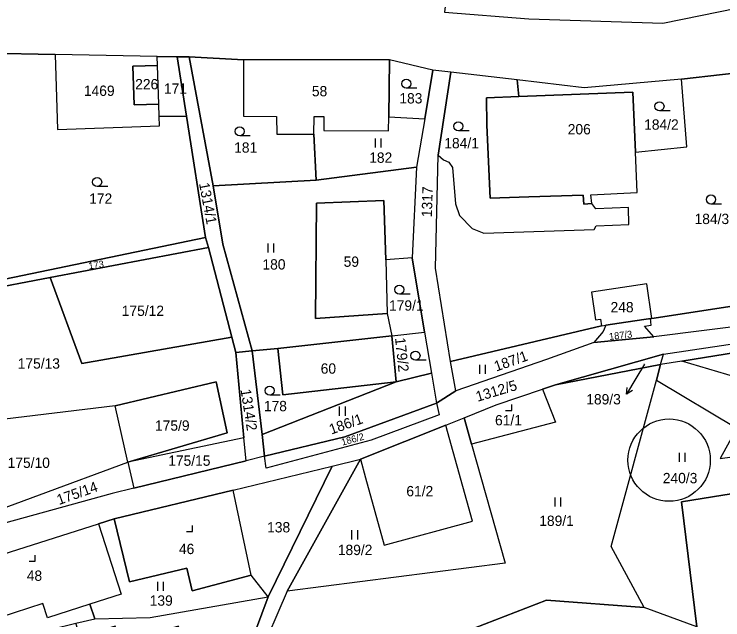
# Model space of a CAD drawing. Extents: x -588699 to -585793, y -1060280 to -1056731.
# Drawn here: x -588042.9 to -587926.2, y -1058215 to -1058115.3 of the extents above; entities that cross this region are included whole.
import ezdxf

# ---------------------------------------------------------------- set-up
doc = ezdxf.new("R2010")
doc.units = 0
for name, color, linetype in [('Druh pozemku', 7, 'Continuous'), ('Parcela nároku', 7, 'Continuous'), ('Parcelní číslo', 7, 'Continuous'), ('Změna katastrální hranice', 7, 'Continuous')]:
    doc.layers.add(name, color=color, linetype=linetype)

msp = doc.modelspace()

# ---------------------------------------------------------------- linework, layer by layer
at = {"layer": 'Druh pozemku'}
for p, q in [((-587976.62, -1058127.5), (-587978.37, -1058127.5)), ((-587934.93, -1058131.23), (-587936.68, -1058131.23)), ((-587968.03, -1058134.51), (-587969.78, -1058134.51)), ((-588004.04, -1058135.36), (-588005.79, -1058135.36)), ((-587983.51, -1058135.76), (-587983.51, -1058137.26)), ((-587982.48, -1058137.26), (-587982.48, -1058135.76)), ((-588027.51, -1058143.7), (-588029.26, -1058143.7)), ((-587926.45, -1058146.57), (-587928.2, -1058146.57)), ((-588001.18, -1058153.07), (-588001.18, -1058154.57)), ((-588000.16, -1058154.57), (-588000.16, -1058153.07)), ((-587977.74, -1058161.42), (-587979.49, -1058161.42)), ((-587975.1, -1058172.28), (-587976.85, -1058172.28)), ((-587966.33, -1058173.04), (-587966.33, -1058174.54)), ((-587965.31, -1058174.54), (-587965.31, -1058173.04)), ((-587999.1, -1058178.05), (-588000.85, -1058178.05)), ((-587989.4, -1058179.93), (-587989.4, -1058181.43)), ((-587988.38, -1058181.43), (-587988.38, -1058179.93)), ((-587933.46, -1058187.53), (-587933.46, -1058189.03)), ((-587932.44, -1058189.03), (-587932.44, -1058187.53)), ((-587953.92, -1058194.89), (-587953.92, -1058196.39)), ((-587952.9, -1058196.39), (-587952.9, -1058194.89)), ((-587987.36, -1058200.3), (-587987.36, -1058201.8)), ((-587986.33, -1058201.8), (-587986.33, -1058200.3)), ((-588019.33, -1058208.76), (-588019.33, -1058210.26)), ((-588018.31, -1058210.26), (-588018.31, -1058208.76))]:
    msp.add_line(p, q, dxfattribs=at)
for points in [[(-587962, -1058180.56), (-587961, -1058180.56), (-587961, -1058179.56)], [(-588014.55, -1058200.49), (-588013.55, -1058200.49), (-588013.55, -1058199.49)], [(-588040.46, -1058205.41), (-588039.46, -1058205.41), (-588039.46, -1058204.41)]]:
    msp.add_lwpolyline(points, dxfattribs=at)
for centre in [(-587978.37, -1058126.75), (-587936.68, -1058130.48), (-587969.78, -1058133.76), (-588005.79, -1058134.61), (-588029.26, -1058142.95), (-587928.2, -1058145.82), (-587979.49, -1058160.67), (-587976.85, -1058171.53), (-588000.85, -1058177.3)]:
    msp.add_circle(centre, 0.75, dxfattribs=at)
at = {"layer": 'Parcela nároku'}
for points in [[(-587905.27, -1058107.44), (-587957.76, -1058103.14), (-587957.46, -1058105.34), (-587971.28, -1058108.32), (-587972.07, -1058115), (-587958.19, -1058116.05), (-587936.11, -1058116.81), (-587902.41, -1058109.85)], [(-588014.55, -1058132.08), (-588011.42, -1058152.1), (-588048.73, -1058159.83), (-588048.14, -1058143.2), (-588047.38, -1058121.73), (-588036.18, -1058121.95), (-588035.78, -1058134.31), (-588019, -1058133.7), (-588019.05, -1058132.15)], [(-588019, -1058133.7), (-588019.05, -1058132.15), (-588019.12, -1058130.13), (-588023.16, -1058130.21), (-588023.37, -1058123.84), (-588019.33, -1058123.76), (-588019.38, -1058122.28), (-588036.18, -1058121.95), (-588035.78, -1058134.31)], [(-588019.38, -1058122.28), (-588016.07, -1058122.34), (-588014.55, -1058132.08), (-588019.05, -1058132.15), (-588019.12, -1058130.13), (-588019.33, -1058123.76)], [(-588010.17, -1058143.59), (-588008.57, -1058153.18), (-588003.75, -1058170.75), (-588006.42, -1058171.01), (-588007.07, -1058168.5), (-588010.91, -1058153.75), (-588011.42, -1058152.1), (-588014.55, -1058132.08), (-588016.07, -1058122.34), (-588014.09, -1058122.32)], [(-587999.7, -1058135.06), (-587993.56, -1058135.06), (-587993.21, -1058142.62), (-588010.17, -1058143.59), (-588014.09, -1058122.32), (-588005.14, -1058122.81), (-588005.15, -1058132.1), (-587999.73, -1058132.15)], [(-588005.14, -1058122.81), (-588005.15, -1058132.1), (-587999.73, -1058132.15), (-587999.7, -1058135.06), (-587993.56, -1058135.06), (-587993.53, -1058132.14), (-587991.91, -1058132.15), (-587991.92, -1058134.48), (-587981.28, -1058134.52), (-587981.23, -1058132.19), (-587981.13, -1058122.84)], [(-587973.98, -1058124.5), (-587981.13, -1058122.84), (-587981.23, -1058132.19), (-587975.33, -1058132.52)], [(-588019.12, -1058130.13), (-588019.33, -1058123.76), (-588023.37, -1058123.84), (-588023.16, -1058130.21)], [(-587971.1, -1058172.51), (-587973.57, -1058157.13), (-587973.1, -1058138.54), (-587971.04, -1058124.84), (-587973.98, -1058124.5), (-587975.33, -1058132.52), (-587976.68, -1058140.49), (-587977.42, -1058155.41), (-587975.36, -1058167.68), (-587974.22, -1058174.45), (-587973.4, -1058179.35), (-587970.19, -1058177.31)], [(-587958.16, -1058145.41), (-587964.55, -1058145.63), (-587965.1, -1058133.6), (-587965.16, -1058129.09), (-587959.84, -1058128.88), (-587960.12, -1058126.1), (-587971.04, -1058124.84), (-587973.1, -1058138.54), (-587972.24, -1058139.31), (-587971.37, -1058139.69), (-587970.75, -1058140.58), (-587970.26, -1058146.51), (-587969.6, -1058148.46), (-587967.49, -1058150.61), (-587965.61, -1058151.36), (-587947.41, -1058150.75), (-587947.11, -1058150.15), (-587941.73, -1058149.94), (-587941.8, -1058147.14), (-587947.17, -1058147.37), (-587947.79, -1058146.5), (-587949.14, -1058146.57), (-587949.23, -1058145.1)], [(-587932.17, -1058137.14), (-587933.06, -1058125.98), (-587949.07, -1058127.46), (-587960.12, -1058126.1), (-587959.84, -1058128.88), (-587941.08, -1058128.16), (-587940.64, -1058138.05)], [(-587940.34, -1058144.65), (-587940.64, -1058138.05), (-587941.08, -1058128.16), (-587959.84, -1058128.88), (-587965.16, -1058129.09), (-587965.1, -1058133.6), (-587964.55, -1058145.63), (-587958.16, -1058145.41), (-587949.23, -1058145.1), (-587949.14, -1058146.57), (-587947.79, -1058146.5), (-587947.99, -1058145.07)], [(-587993.53, -1058132.14), (-587991.91, -1058132.15), (-587991.92, -1058134.48), (-587981.28, -1058134.52), (-587981.23, -1058132.19), (-587975.33, -1058132.52), (-587976.68, -1058140.49), (-587993.21, -1058142.62), (-587993.56, -1058135.06)], [(-587981.5, -1058164.62), (-587980.73, -1058168.26), (-587999.52, -1058170.38), (-588003.75, -1058170.75), (-588008.57, -1058153.18), (-588010.17, -1058143.59), (-587993.21, -1058142.62), (-587976.68, -1058140.49), (-587977.42, -1058155.41), (-587981.75, -1058155.74), (-587982.03, -1058146.01), (-587993.12, -1058146.43), (-587993.28, -1058165.44)], [(-587993.12, -1058146.43), (-587982.03, -1058146.01), (-587981.75, -1058155.74), (-587981.5, -1058164.62), (-587993.28, -1058165.44)], [(-588011.42, -1058152.1), (-588010.91, -1058153.75), (-588036.97, -1058158.68), (-588048.49, -1058160.86), (-588048.73, -1058159.83)], [(-588036.97, -1058158.68), (-588010.91, -1058153.75), (-588007.07, -1058168.5), (-588031.79, -1058172.85)], [(-587977.42, -1058155.41), (-587981.75, -1058155.74), (-587981.5, -1058164.62), (-587980.73, -1058168.26), (-587975.36, -1058167.68)], [(-588036.97, -1058158.68), (-588031.79, -1058172.85), (-588007.07, -1058168.5), (-588006.42, -1058171.01), (-588005.12, -1058185.1), (-588024.21, -1058189.07), (-588007.87, -1058184.23), (-588009.65, -1058175.86), (-588026.28, -1058179.79), (-588046.31, -1058182.23), (-588047.18, -1058174.61), (-588060.82, -1058175.82), (-588064.06, -1058164.47), (-588048.49, -1058160.86)], [(-587937.93, -1058165.4), (-587938.77, -1058159.7), (-587947.88, -1058161.1), (-587947.21, -1058165.65), (-587946.41, -1058165.53), (-587946.23, -1058166.64), (-587945.49, -1058166.52), (-587944.4, -1058166.36), (-587943.34, -1058166.2), (-587939.28, -1058165.6), (-587938.5, -1058165.49), (-587938.13, -1058165.42)], [(-587937.93, -1058165.4), (-587904.02, -1058160.23), (-587904, -1058164.19), (-587937.63, -1058168.42), (-587939.12, -1058166.7), (-587938.04, -1058166.53), (-587938.13, -1058165.42)], [(-587937.19, -1058175.57), (-587923.93, -1058183.49), (-587926.7, -1058188.48), (-587898.86, -1058184.66), (-587888.94, -1058185.21), (-587884.21, -1058183.4), (-587886.93, -1058176.48), (-587883.4, -1058175.08), (-587886.16, -1058167.86), (-587887.26, -1058165.09), (-587878.46, -1058165.39), (-587874.84, -1058186.24), (-587933.04, -1058195.62), (-587930.55, -1058216.22), (-587939.22, -1058213.03), (-587944.64, -1058202.99)], [(-587887.26, -1058165.09), (-587903.82, -1058167.75), (-587903.56, -1058168.92), (-587919.66, -1058176.42), (-587933.02, -1058172.44), (-587936.49, -1058173), (-587937.19, -1058175.57), (-587923.93, -1058183.49), (-587926.7, -1058188.48), (-587898.86, -1058184.66), (-587903.56, -1058174.48), (-587886.16, -1058167.86)], [(-587936.03, -1058171.3), (-587904.1, -1058166.51), (-587887.26, -1058165.09), (-587903.82, -1058167.75), (-587933.02, -1058172.44), (-587936.49, -1058173)], [(-587945.97, -1058167.58), (-587947.48, -1058169.39), (-587937.63, -1058168.42), (-587939.12, -1058166.7), (-587938.04, -1058166.53), (-587938.13, -1058165.42), (-587938.5, -1058165.49), (-587939.28, -1058165.6), (-587943.34, -1058166.2), (-587944.4, -1058166.36), (-587945.49, -1058166.52)], [(-587878.46, -1058165.39), (-587852.6, -1058169.68), (-587842.96, -1058169.39), (-587845.87, -1058217.7), (-587852.17, -1058218.46), (-587874.99, -1058223.36), (-587893.08, -1058224.69), (-587921.7, -1058222.21), (-587922.75, -1058226.1), (-587927.3, -1058243.08), (-587929.2, -1058227.37), (-587930.55, -1058216.22), (-587933.04, -1058195.62), (-587874.84, -1058186.24)], [(-587971.1, -1058172.51), (-587946.23, -1058166.64), (-587945.49, -1058166.52), (-587945.97, -1058167.58), (-587947.48, -1058169.39), (-587955.25, -1058172.16), (-587970.19, -1058177.31)], [(-587980.73, -1058168.26), (-587980.05, -1058175.87), (-587998.67, -1058177.99), (-587999.52, -1058170.38)], [(-587975.36, -1058167.68), (-587974.22, -1058174.45), (-587980.05, -1058175.87), (-587980.73, -1058168.26)], [(-587903.82, -1058167.75), (-587903.56, -1058168.92), (-587919.66, -1058176.42), (-587933.02, -1058172.44)], [(-588002.11, -1058184.55), (-588001.69, -1058188.1), (-588004.73, -1058188.84), (-588005.12, -1058185.1), (-588006.42, -1058171.01), (-588003.75, -1058170.75)], [(-588003.75, -1058170.75), (-587999.52, -1058170.38), (-587998.67, -1058177.99), (-587980.05, -1058175.87), (-588002.11, -1058184.55)], [(-587936.03, -1058171.3), (-587953.79, -1058176.32), (-587936.49, -1058173)], [(-587962.1, -1058205.72), (-587997.97, -1058210.3), (-588002.76, -1058221.42), (-588002.42, -1058228.61), (-587986.11, -1058221.3), (-587982.5, -1058222.32), (-587955.25, -1058211.83), (-587939.22, -1058213.03), (-587944.64, -1058202.99), (-587937.19, -1058175.57), (-587936.49, -1058173), (-587953.79, -1058176.32), (-587955.95, -1058177.06), (-587953.8, -1058182.5), (-587967.62, -1058186.12)], [(-587974.22, -1058174.45), (-587973.4, -1058179.35), (-587988.48, -1058184.92), (-588001.69, -1058188.1), (-588002.11, -1058184.55), (-587980.05, -1058175.87)], [(-588009.65, -1058175.86), (-588007.87, -1058184.23), (-588024.21, -1058189.07), (-588026.28, -1058179.79)], [(-587955.95, -1058177.06), (-587953.8, -1058182.5), (-587967.62, -1058186.12), (-587968.85, -1058181.77), (-587963.54, -1058179.65)], [(-588024.21, -1058189.07), (-588026.28, -1058179.79), (-588046.31, -1058182.23), (-588057.57, -1058186.43), (-588053.33, -1058199.85)], [(-587988.48, -1058184.92), (-587973.4, -1058179.35), (-587972.95, -1058181.31), (-587984.15, -1058185.44), (-588001.45, -1058190.08), (-588001.69, -1058188.1)], [(-587971.86, -1058182.98), (-587968.85, -1058181.77), (-587967.62, -1058186.12), (-587962.1, -1058205.72), (-587997.97, -1058210.3), (-587985.91, -1058188.6), (-587985.06, -1058191.68), (-587982.01, -1058202.74), (-587967.46, -1058198.8), (-587971.57, -1058184.04)], [(-587978.59, -1058185.67), (-587985.91, -1058188.6), (-587985.06, -1058191.68), (-587982.01, -1058202.74), (-587967.46, -1058198.8), (-587971.57, -1058184.04), (-587971.86, -1058182.98)], [(-588005.12, -1058185.1), (-588024.21, -1058189.07), (-588023.22, -1058193.36), (-588004.73, -1058188.84)], [(-588024.21, -1058189.07), (-588023.22, -1058193.36), (-588026.8, -1058194.23), (-588052.9, -1058201.43), (-588053.33, -1058199.85)], [(-588006.88, -1058193.67), (-587990.55, -1058189.72), (-588001.08, -1058211.26), (-588003.88, -1058207.71)], [(-588003.88, -1058207.71), (-588006.88, -1058193.67), (-588026.47, -1058198.42), (-588023.93, -1058208.8), (-588014.49, -1058206.52), (-588013.59, -1058210.28)], [(-588023.93, -1058208.8), (-588026.47, -1058198.42), (-588029.03, -1058199.24), (-588025.28, -1058210.8), (-588030.46, -1058212.46), (-588029.61, -1058214.86), (-588020.54, -1058214.66), (-588001.08, -1058211.26), (-588003.88, -1058207.71), (-588013.59, -1058210.28), (-588014.49, -1058206.52)], [(-588048.39, -1058205.39), (-588029.03, -1058199.24), (-588025.28, -1058210.8), (-588030.46, -1058212.46), (-588037.44, -1058214.7), (-588038.19, -1058212.33), (-588045.35, -1058214.64)], [(-588037.44, -1058214.7), (-588038.19, -1058212.33), (-588045.35, -1058214.64), (-588048.39, -1058205.39), (-588058.38, -1058208.56), (-588053.92, -1058217.06), (-588052.23, -1058220.29), (-588047.8, -1058219.23), (-588036.77, -1058216.58), (-588032.79, -1058215.62), (-588029.61, -1058214.86), (-588030.46, -1058212.46)], [(-588032.79, -1058215.62), (-588029.61, -1058214.86), (-588020.54, -1058214.66), (-588001.08, -1058211.26), (-588005.42, -1058222.88), (-588013.42, -1058225.65), (-588015.88, -1058216.1), (-588025.29, -1058218.83), (-588026.29, -1058216.07), (-588032.03, -1058217.82)], [(-587939.22, -1058213.03), (-587955.25, -1058211.83), (-587982.5, -1058222.32), (-587986.11, -1058221.3), (-588002.42, -1058228.61), (-588002.11, -1058235.37), (-587998.02, -1058244.21), (-587982.98, -1058242.73), (-587929.2, -1058227.37), (-587930.55, -1058216.22)]]:
    msp.add_lwpolyline(points, close=True, dxfattribs=at)
for points in [[(-587879.59, -1058109.01), (-587910.22, -1058119.99), (-587919.57, -1058124.47), (-587933.06, -1058125.98), (-587949.07, -1058127.46), (-587960.12, -1058126.1), (-587971.04, -1058124.84), (-587973.98, -1058124.5), (-587981.13, -1058122.84), (-588005.14, -1058122.81), (-588014.09, -1058122.32), (-588016.07, -1058122.34), (-588019.38, -1058122.28), (-588036.18, -1058121.95), (-588047.38, -1058121.73), (-588054.87, -1058121.87), (-588058.28, -1058121.93), (-588062.02, -1058121.79), (-588073.1, -1058121.39), (-588081.23, -1058121.1), (-588115.84, -1058119.95), (-588127.93, -1058119.84), (-588133.87, -1058117.14), (-588172.01, -1058109.5)], [(-587972.07, -1058115), (-587958.19, -1058116.05), (-587936.11, -1058116.81), (-587902.41, -1058109.85)], [(-587904.02, -1058160.23), (-587937.93, -1058165.4), (-587938.77, -1058159.7), (-587947.88, -1058161.1), (-587947.21, -1058165.65), (-587946.41, -1058165.53), (-587946.23, -1058166.64), (-587971.1, -1058172.51), (-587973.57, -1058157.13), (-587973.1, -1058138.54), (-587972.24, -1058139.31), (-587971.37, -1058139.69), (-587970.75, -1058140.58), (-587970.26, -1058146.51), (-587969.6, -1058148.46), (-587967.49, -1058150.61), (-587965.61, -1058151.36), (-587947.41, -1058150.75), (-587947.11, -1058150.15), (-587941.73, -1058149.94), (-587941.8, -1058147.14), (-587947.17, -1058147.37), (-587947.79, -1058146.5), (-587947.99, -1058145.07), (-587940.34, -1058144.65), (-587940.64, -1058138.05), (-587932.17, -1058137.14), (-587933.06, -1058125.98), (-587919.57, -1058124.47)], [(-587808.9, -1058162.63), (-587840.39, -1058167.44), (-587852.03, -1058167.69), (-587888.68, -1058161.9), (-587901.92, -1058163.88), (-587904, -1058164.19), (-587937.63, -1058168.42), (-587947.48, -1058169.39), (-587955.25, -1058172.16), (-587970.19, -1058177.31), (-587973.4, -1058179.35), (-587972.95, -1058181.31), (-587984.15, -1058185.44), (-588001.45, -1058190.08), (-588001.69, -1058188.1), (-588004.73, -1058188.84), (-588023.22, -1058193.36), (-588026.8, -1058194.23), (-588052.9, -1058201.43)], [(-588048.39, -1058205.39), (-588029.03, -1058199.24), (-588026.47, -1058198.42), (-588006.88, -1058193.67), (-587990.55, -1058189.72), (-587985.91, -1058188.6), (-587978.59, -1058185.67), (-587971.86, -1058182.98), (-587968.85, -1058181.77), (-587963.54, -1058179.65), (-587955.95, -1058177.06), (-587953.79, -1058176.32), (-587936.03, -1058171.3), (-587904.1, -1058166.51), (-587887.26, -1058165.09), (-587878.46, -1058165.39), (-587852.6, -1058169.68), (-587842.96, -1058169.39), (-587834.19, -1058169.13), (-587817.41, -1058167.23)], [(-588043.9, -1058278.57), (-588040.35, -1058274.68), (-588035.53, -1058269.41), (-588026.72, -1058262.49), (-588019.94, -1058256.55), (-588010.93, -1058249.05), (-588005.9, -1058234.96), (-588005.42, -1058222.88), (-588001.08, -1058211.26), (-587990.55, -1058189.72), (-587985.91, -1058188.6), (-587997.97, -1058210.3), (-588002.76, -1058221.42), (-588002.42, -1058228.61), (-588002.11, -1058235.37), (-588006.72, -1058248.64), (-588010.89, -1058252.97), (-588013.86, -1058255.37), (-588014.78, -1058256.14), (-588032.33, -1058270.74), (-588037.18, -1058276.01), (-588042.26, -1058285.27)]]:
    msp.add_lwpolyline(points, dxfattribs=at)
at = {"layer": 'Parcelní číslo'}
for p, q in [((-587939.17, -1058172.96), (-587940.55, -1058175.29)), ((-587940.55, -1058175.29), (-587942.08, -1058177.87))]:
    msp.add_line(p, q, dxfattribs=at)
msp.add_lwpolyline([(-587941.14, -1058177.27), (-587942.08, -1058177.87), (-587942, -1058176.76)], dxfattribs=at)
at = {"layer": 'Změna katastrální hranice'}
msp.add_circle((-587935.09, -1058188.75), 6.78, dxfattribs=at)

# ---------------------------------------------------------------- texts
at = {"layer": 'Parcela nároku'}
for s, height, p in [('226', 1.7, (-588022.99, -1058127.68)), ('1469', 1.7, (-588031.44, -1058128.76)), ('171', 1.7, (-588018.26, -1058128.41)), ('58', 1.7, (-587993.9, -1058128.83)), ('183', 1.7, (-587979.5, -1058130.01)), ('206', 1.7, (-587951.78, -1058135.1)), ('184/2', 1.7, (-587939.2, -1058134.33)), ('184/1', 1.7, (-587972.1, -1058137.39)), ('181', 1.7, (-588006.7, -1058138.11)), ('182', 1.7, (-587984.47, -1058139.78)), ('172', 1.7, (-588030.57, -1058146.53)), ('184/3', 1.7, (-587930.9, -1058149.87)), ('180', 1.7, (-588002.04, -1058157.36)), ('59', 1.7, (-587988.67, -1058156.91)), ('179/1', 1.7, (-587981.2, -1058164.13)), ('248', 1.7, (-587944.73, -1058164.4)), ('175/12', 1.7, (-588025.2, -1058165)), ('175/13', 1.7, (-588042.33, -1058173.68)), ('60', 1.7, (-587992.45, -1058174.51)), ('189/3', 0.1, (-587939.34, -1058172.96)), ('178', 1.7, (-588001.81, -1058180.69)), ('61/1', 1.7, (-587963.75, -1058183.02)), ('175/9', 1.7, (-588019.73, -1058183.9)), ('175/10', 1.7, (-588043.99, -1058190.03)), ('175/15', 1.7, (-588017.55, -1058189.68)), ('240/3', 1.7, (-587936.13, -1058192.55)), ('61/2', 1.7, (-587978.35, -1058194.7)), ('189/1', 1.7, (-587956.47, -1058199.58)), ('138', 1.7, (-588001.27, -1058200.65)), ('46', 1.7, (-588015.79, -1058204.22)), ('189/2', 1.7, (-587989.63, -1058204.38)), ('48', 1.7, (-588040.84, -1058208.62)), ('139', 1.7, (-588020.6, -1058212.72))]:
    msp.add_text(s, height=height, dxfattribs=at).set_placement(p)
for s, height, rotation, p in [('1314/1', 1.7, 280.6313, (-588012.49, -1058143.19)), ('1317', 1.7, 88.0574, (-587974.16, -1058148.76)), ('173', 1.14, 7.7294, (-588030.61, -1058157.32)), ('187/3', 1.14, 6.6026, (-587944.91, -1058168.97)), ('179/2', 1.7, 275.9916, (-587980.22, -1058168.64)), ('187/1', 1.7, 19.4405, (-587963.55, -1058174.17)), ('1312/5', 1.7, 16.8017, (-587966.63, -1058179.15)), ('1314/2', 1.7, 278.9581, (-588005.65, -1058177.16)), ('186/1', 1.7, 19.7623, (-587990.7, -1058184.55)), ('186/2', 1.14, 15.3272, (-587988.88, -1058186.36)), ('175/14', 1.7, 19.6493, (-588035.54, -1058196.15))]:
    msp.add_text(s, height=height, rotation=rotation, dxfattribs=at).set_placement(p)
at = {"layer": 'Parcelní číslo'}
msp.add_text('189/3', height=1.7, dxfattribs=at).set_placement((-587948.73, -1058179.57))

doc.saveas('drawing.dxf')
